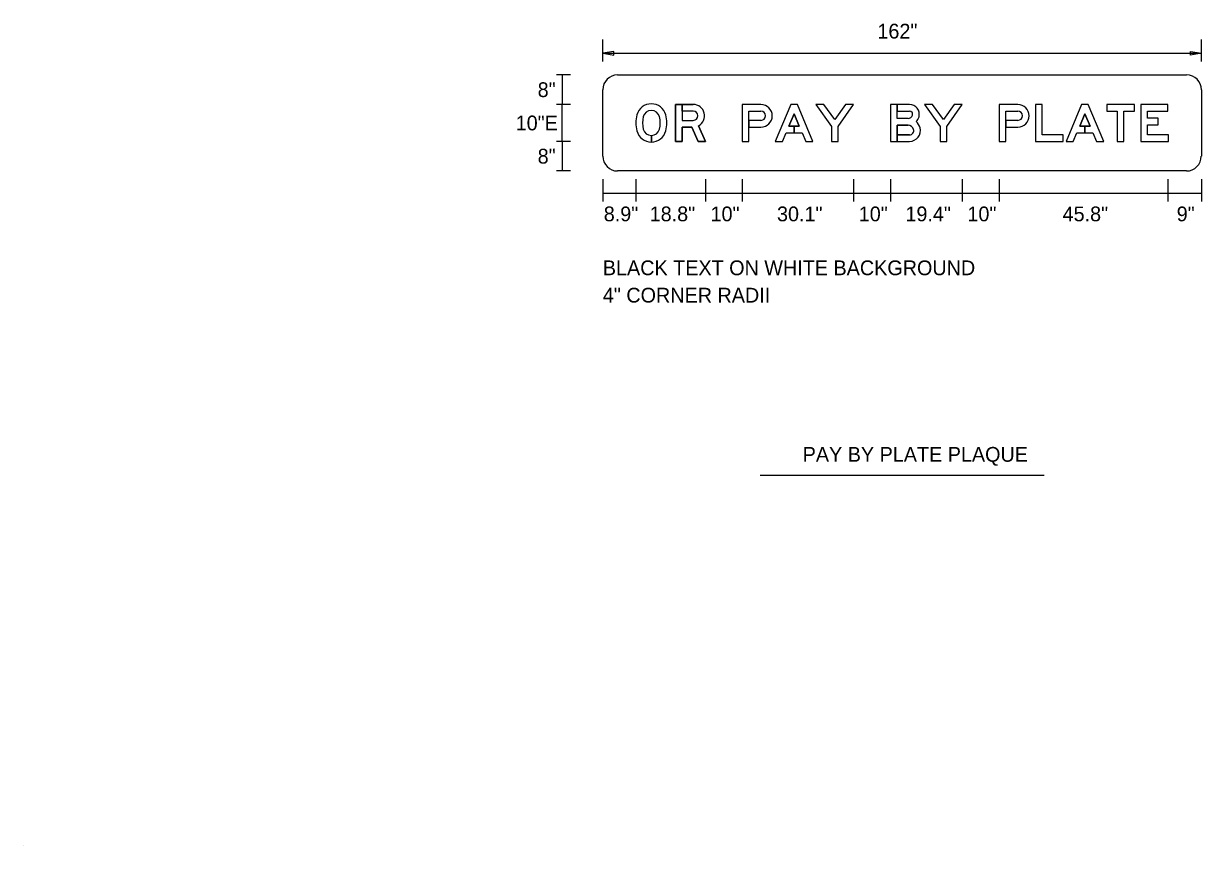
# Model space of a CAD drawing. Extents: x 10268312 to 10268472, y 2142583 to 2142688.
# Drawn here: x 10268312.2 to 10268372, y 2142583.3 to 2142625 of the extents above; entities that cross this region are included whole.
import ezdxf

# ---------------------------------------------------------------- set-up
doc = ezdxf.new("R2010")
doc.units = 0
for name, color, linetype in [('AdhocPoint_dp', 7, 'Continuous'), ('GSBWFill', 7, 'Continuous'), ('GSDims', 7, 'Continuous'), ('SignPanel', 7, 'Continuous'), ('TextLabel', 7, 'Continuous'), ('TextMisc', 7, 'Continuous')]:
    doc.layers.add(name, color=color, linetype=linetype)

msp = doc.modelspace()

# ---------------------------------------------------------------- linework, layer by layer
at = {"layer": 'AdhocPoint_dp'}
msp.add_line((10268312.23, 2142583.281), (10268312.23, 2142583.281), dxfattribs=at)
at = {"layer": 'GSBWFill'}
for p, q in [((10268342.368, 2142622.39), (10268371.236, 2142622.39)), ((10268341.618, 2142618.265), (10268341.618, 2142621.64)), ((10268371.986, 2142621.64), (10268371.986, 2142618.265)), ((10268371.236, 2142617.515), (10268342.368, 2142617.515))]:
    msp.add_line(p, q, dxfattribs=at)
for centre, start, end in [((10268342.368, 2142621.64), 90, 180), ((10268371.236, 2142621.64), 0, 90), ((10268342.368, 2142618.265), 180, 270), ((10268371.229, 2142618.265), 270, 0)]:
    msp.add_arc(centre, 0.75, start, end, dxfattribs=at)
at = {"layer": 'GSDims'}
for p, q in [((10268341.618, 2142623.07), (10268341.618, 2142624.195)), ((10268371.986, 2142623.07), (10268371.986, 2142624.195)), ((10268341.618, 2142623.492), (10268371.986, 2142623.492)), ((10268339.977, 2142622.39), (10268339.274, 2142622.39)), ((10268339.555, 2142622.39), (10268339.555, 2142620.89)), ((10268339.977, 2142620.89), (10268339.274, 2142620.89)), ((10268339.555, 2142619.015), (10268339.555, 2142620.89)), ((10268339.977, 2142619.015), (10268339.274, 2142619.015)), ((10268339.555, 2142619.015), (10268339.555, 2142617.515)), ((10268339.977, 2142617.515), (10268339.274, 2142617.515)), ((10268341.618, 2142617.093), (10268341.618, 2142615.968)), ((10268343.294, 2142617.093), (10268343.294, 2142615.968)), ((10268346.818, 2142617.093), (10268346.818, 2142615.968)), ((10268348.693, 2142617.093), (10268348.693, 2142615.968)), ((10268354.336, 2142617.093), (10268354.336, 2142615.968)), ((10268356.212, 2142617.093), (10268356.212, 2142615.968)), ((10268359.849, 2142617.093), (10268359.849, 2142615.968)), ((10268361.724, 2142617.093), (10268361.724, 2142615.968)), ((10268370.284, 2142617.093), (10268370.284, 2142615.968)), ((10268371.986, 2142617.093), (10268371.986, 2142615.968)), ((10268341.618, 2142616.39), (10268343.294, 2142616.39)), ((10268343.294, 2142616.39), (10268346.818, 2142616.39)), ((10268346.818, 2142616.39), (10268348.693, 2142616.39)), ((10268348.693, 2142616.39), (10268354.336, 2142616.39)), ((10268354.336, 2142616.39), (10268356.212, 2142616.39)), ((10268356.212, 2142616.39), (10268359.849, 2142616.39)), ((10268359.849, 2142616.39), (10268361.724, 2142616.39)), ((10268361.724, 2142616.39), (10268370.284, 2142616.39)), ((10268370.284, 2142616.39), (10268371.986, 2142616.39)), ((10268349.596, 2142602.067), (10268364.009, 2142602.067))]:
    msp.add_line(p, q, dxfattribs=at)
for points in [[(10268341.618, 2142623.492), (10268342.181, 2142623.398), (10268342.181, 2142623.586)], [(10268371.986, 2142623.492), (10268371.424, 2142623.398), (10268371.424, 2142623.586)]]:
    msp.add_lwpolyline(points, close=True, dxfattribs=at)
at = {"layer": 'SignPanel'}
for p, q in [((10268349.03, 2142620.552), (10268349.64, 2142620.552)), ((10268349.03, 2142620.552), (10268349.64, 2142620.552)), ((10268349.03, 2142620.552), (10268349.64, 2142620.552)), ((10268362.062, 2142620.552), (10268362.671, 2142620.552)), ((10268362.062, 2142620.552), (10268362.671, 2142620.552)), ((10268362.062, 2142620.552), (10268362.671, 2142620.552)), ((10268349.03, 2142619.746), (10268349.64, 2142619.746)), ((10268362.062, 2142619.746), (10268362.671, 2142619.746)), ((10268344.08, 2142618.982), (10268344.08, 2142619.319)), ((10268344.08, 2142619.319), (10268344.08, 2142618.982)), ((10268344.08, 2142618.982), (10268344.08, 2142619.319)), ((10268344.08, 2142619.319), (10268344.08, 2142618.982)), ((10268356.212, 2142619.015), (10268357.177, 2142619.015))]:
    msp.add_line(p, q, dxfattribs=at)
for points in [[(10268346.206, 2142620.89), (10268345.299, 2142620.89), (10268345.299, 2142619.015), (10268345.637, 2142619.015), (10268345.637, 2142619.746), (10268346.133, 2142619.746), (10268346.45, 2142619.015), (10268346.818, 2142619.015), (10268346.473, 2142619.812)], [(10268346.473, 2142619.812), (10268346.818, 2142619.015), (10268346.45, 2142619.015), (10268346.133, 2142619.746), (10268345.637, 2142619.746), (10268345.637, 2142619.015), (10268345.299, 2142619.015), (10268345.299, 2142620.89), (10268345.637, 2142620.89), (10268345.637, 2142620.083), (10268346.206, 2142620.083)], [(10268346.473, 2142619.812), (10268346.818, 2142619.015), (10268346.45, 2142619.015), (10268346.133, 2142619.746), (10268345.637, 2142619.746), (10268345.637, 2142619.015), (10268345.299, 2142619.015), (10268345.299, 2142620.89), (10268345.637, 2142620.89), (10268345.637, 2142620.083), (10268346.206, 2142620.083)], [(10268345.637, 2142620.552), (10268345.637, 2142620.89), (10268346.206, 2142620.89)], [(10268345.637, 2142620.552), (10268345.637, 2142620.89), (10268346.206, 2142620.89)], [(10268349.64, 2142620.89), (10268348.693, 2142620.89), (10268348.693, 2142619.015), (10268349.03, 2142619.015), (10268349.03, 2142619.746)], [(10268349.64, 2142620.89), (10268348.693, 2142620.89), (10268348.693, 2142619.015), (10268349.03, 2142619.015), (10268349.03, 2142620.552)], [(10268349.64, 2142620.89), (10268348.693, 2142620.89), (10268348.693, 2142619.015), (10268349.03, 2142619.015), (10268349.03, 2142620.552)], [(10268357.177, 2142620.89), (10268356.212, 2142620.89), (10268356.212, 2142619.015)], [(10268357.105, 2142620.177), (10268356.549, 2142620.177), (10268356.549, 2142620.89), (10268356.212, 2142620.89), (10268356.212, 2142619.015), (10268356.549, 2142619.015)], [(10268357.105, 2142620.177), (10268356.549, 2142620.177), (10268356.549, 2142620.89), (10268356.212, 2142620.89), (10268356.212, 2142619.015), (10268356.549, 2142619.015)], [(10268357.177, 2142620.89), (10268356.549, 2142620.89), (10268356.549, 2142620.552), (10268357.177, 2142620.552)], [(10268357.177, 2142620.89), (10268356.549, 2142620.89), (10268356.549, 2142620.552), (10268357.177, 2142620.552)], [(10268362.671, 2142620.89), (10268361.724, 2142620.89), (10268361.724, 2142619.015), (10268362.062, 2142619.015), (10268362.062, 2142619.746)], [(10268362.671, 2142620.89), (10268361.724, 2142620.89), (10268361.724, 2142619.015), (10268362.062, 2142619.015), (10268362.062, 2142620.552)], [(10268362.671, 2142620.89), (10268361.724, 2142620.89), (10268361.724, 2142619.015), (10268362.062, 2142619.015), (10268362.062, 2142620.552)], [(10268346.206, 2142620.552), (10268345.637, 2142620.552), (10268345.637, 2142620.083), (10268346.206, 2142620.083)], [(10268346.206, 2142620.552), (10268345.637, 2142620.552)], [(10268346.206, 2142620.552), (10268345.637, 2142620.552)], [(10268349.64, 2142620.083), (10268349.03, 2142620.083), (10268349.03, 2142620.552)], [(10268349.64, 2142620.083), (10268349.03, 2142620.083), (10268349.03, 2142619.746), (10268349.64, 2142619.746)], [(10268349.64, 2142620.083), (10268349.03, 2142620.083), (10268349.03, 2142619.746), (10268349.64, 2142619.746)], [(10268357.105, 2142620.177), (10268356.549, 2142620.177), (10268356.549, 2142620.552), (10268357.177, 2142620.552)], [(10268362.671, 2142620.083), (10268362.062, 2142620.083), (10268362.062, 2142620.552)], [(10268362.671, 2142620.083), (10268362.062, 2142620.083), (10268362.062, 2142619.746), (10268362.671, 2142619.746)], [(10268362.671, 2142620.083), (10268362.062, 2142620.083), (10268362.062, 2142619.746), (10268362.671, 2142619.746)], [(10268357.105, 2142619.84), (10268356.549, 2142619.84), (10268356.549, 2142619.352), (10268357.177, 2142619.352)], [(10268356.549, 2142619.015), (10268356.549, 2142619.84), (10268357.105, 2142619.84)], [(10268356.549, 2142619.015), (10268356.549, 2142619.84), (10268357.105, 2142619.84)], [(10268357.177, 2142619.352), (10268356.549, 2142619.352), (10268356.549, 2142619.015), (10268357.177, 2142619.015)], [(10268357.177, 2142619.352), (10268356.549, 2142619.352), (10268356.549, 2142619.015), (10268357.177, 2142619.015)]]:
    msp.add_lwpolyline(points, dxfattribs=at)
for points in [[(10268350.913, 2142619.455), (10268351.723, 2142619.455), (10268351.908, 2142619.015), (10268352.274, 2142619.015), (10268351.487, 2142620.89), (10268351.149, 2142620.89), (10268350.362, 2142619.015), (10268350.728, 2142619.015)], [(10268351.581, 2142619.793), (10268351.318, 2142619.793), (10268351.318, 2142619.455), (10268351.723, 2142619.455), (10268351.908, 2142619.015), (10268352.274, 2142619.015), (10268351.487, 2142620.89), (10268351.149, 2142620.89), (10268350.362, 2142619.015), (10268350.728, 2142619.015), (10268350.913, 2142619.455), (10268351.318, 2142619.455), (10268351.318, 2142619.793), (10268351.054, 2142619.793), (10268351.318, 2142620.42)], [(10268351.581, 2142619.793), (10268351.318, 2142619.793), (10268351.318, 2142619.455), (10268351.723, 2142619.455), (10268351.908, 2142619.015), (10268352.274, 2142619.015), (10268351.487, 2142620.89), (10268351.149, 2142620.89), (10268350.362, 2142619.015), (10268350.728, 2142619.015), (10268350.913, 2142619.455), (10268351.318, 2142619.455), (10268351.318, 2142619.793), (10268351.054, 2142619.793), (10268351.318, 2142620.42)], [(10268353.549, 2142619.774), (10268354.337, 2142620.89), (10268353.923, 2142620.89), (10268353.38, 2142620.12), (10268352.837, 2142620.89), (10268352.424, 2142620.89), (10268353.212, 2142619.774), (10268353.212, 2142619.015), (10268353.549, 2142619.015)], [(10268353.549, 2142619.774), (10268354.337, 2142620.89), (10268353.923, 2142620.89), (10268353.38, 2142620.12), (10268352.837, 2142620.89), (10268352.424, 2142620.89), (10268353.212, 2142619.774), (10268353.212, 2142619.015), (10268353.549, 2142619.015)], [(10268353.549, 2142619.774), (10268354.337, 2142620.89), (10268353.923, 2142620.89), (10268353.38, 2142620.12), (10268352.837, 2142620.89), (10268352.424, 2142620.89), (10268353.212, 2142619.774), (10268353.212, 2142619.015), (10268353.549, 2142619.015)], [(10268359.062, 2142619.774), (10268359.849, 2142620.89), (10268359.436, 2142620.89), (10268358.893, 2142620.12), (10268358.35, 2142620.89), (10268357.937, 2142620.89), (10268358.724, 2142619.774), (10268358.724, 2142619.015), (10268359.062, 2142619.015)], [(10268359.062, 2142619.774), (10268359.849, 2142620.89), (10268359.436, 2142620.89), (10268358.893, 2142620.12), (10268358.35, 2142620.89), (10268357.937, 2142620.89), (10268358.724, 2142619.774), (10268358.724, 2142619.015), (10268359.062, 2142619.015)], [(10268359.062, 2142619.774), (10268359.849, 2142620.89), (10268359.436, 2142620.89), (10268358.893, 2142620.12), (10268358.35, 2142620.89), (10268357.937, 2142620.89), (10268358.724, 2142619.774), (10268358.724, 2142619.015), (10268359.062, 2142619.015)], [(10268364.968, 2142619.015), (10268364.968, 2142619.343), (10268363.899, 2142619.343), (10268363.899, 2142620.89), (10268363.562, 2142620.89), (10268363.562, 2142619.015)], [(10268364.968, 2142619.015), (10268364.968, 2142619.343), (10268363.899, 2142619.343), (10268363.899, 2142620.89), (10268363.562, 2142620.89), (10268363.562, 2142619.015)], [(10268364.968, 2142619.015), (10268364.968, 2142619.343), (10268363.899, 2142619.343), (10268363.899, 2142620.89), (10268363.562, 2142620.89), (10268363.562, 2142619.015)], [(10268365.669, 2142619.455), (10268366.479, 2142619.455), (10268366.664, 2142619.015), (10268367.03, 2142619.015), (10268366.243, 2142620.89), (10268365.905, 2142620.89), (10268365.118, 2142619.015), (10268365.484, 2142619.015)], [(10268366.338, 2142619.793), (10268366.074, 2142619.793), (10268366.074, 2142619.455), (10268366.479, 2142619.455), (10268366.664, 2142619.015), (10268367.03, 2142619.015), (10268366.243, 2142620.89), (10268365.905, 2142620.89), (10268365.118, 2142619.015), (10268365.484, 2142619.015), (10268365.669, 2142619.455), (10268366.074, 2142619.455), (10268366.074, 2142619.793), (10268365.811, 2142619.793), (10268366.074, 2142620.42)], [(10268366.338, 2142619.793), (10268366.074, 2142619.793), (10268366.074, 2142619.455), (10268366.479, 2142619.455), (10268366.664, 2142619.015), (10268367.03, 2142619.015), (10268366.243, 2142620.89), (10268365.905, 2142620.89), (10268365.118, 2142619.015), (10268365.484, 2142619.015), (10268365.669, 2142619.455), (10268366.074, 2142619.455), (10268366.074, 2142619.793), (10268365.811, 2142619.793), (10268366.074, 2142620.42)], [(10268367.18, 2142620.552), (10268367.715, 2142620.552), (10268367.715, 2142619.015), (10268368.052, 2142619.015), (10268368.052, 2142620.552), (10268368.587, 2142620.552), (10268368.587, 2142620.89), (10268367.18, 2142620.89)], [(10268367.18, 2142620.552), (10268367.715, 2142620.552), (10268367.715, 2142619.015), (10268368.052, 2142619.015), (10268368.052, 2142620.552), (10268368.587, 2142620.552), (10268368.587, 2142620.89), (10268367.18, 2142620.89)], [(10268367.18, 2142620.552), (10268367.715, 2142620.552), (10268367.715, 2142619.015), (10268368.052, 2142619.015), (10268368.052, 2142620.552), (10268368.587, 2142620.552), (10268368.587, 2142620.89), (10268367.18, 2142620.89)], [(10268370.312, 2142619.352), (10268369.243, 2142619.352), (10268369.243, 2142619.856), (10268369.796, 2142619.856), (10268369.796, 2142620.194), (10268369.243, 2142620.194), (10268369.243, 2142620.552), (10268370.284, 2142620.552), (10268370.284, 2142620.89), (10268368.905, 2142620.89), (10268368.905, 2142619.015), (10268370.312, 2142619.015)], [(10268370.312, 2142619.352), (10268369.243, 2142619.352), (10268369.243, 2142619.856), (10268369.796, 2142619.856), (10268369.796, 2142620.194), (10268369.243, 2142620.194), (10268369.243, 2142620.552), (10268370.284, 2142620.552), (10268370.284, 2142620.89), (10268368.905, 2142620.89), (10268368.905, 2142619.015), (10268370.312, 2142619.015)], [(10268370.312, 2142619.352), (10268369.243, 2142619.352), (10268369.243, 2142619.856), (10268369.796, 2142619.856), (10268369.796, 2142620.194), (10268369.243, 2142620.194), (10268369.243, 2142620.552), (10268370.284, 2142620.552), (10268370.284, 2142620.89), (10268368.905, 2142620.89), (10268368.905, 2142619.015), (10268370.312, 2142619.015)], [(10268351.581, 2142619.793), (10268351.318, 2142620.42), (10268351.054, 2142619.793)], [(10268366.338, 2142619.793), (10268366.074, 2142620.42), (10268365.811, 2142619.793)]]:
    msp.add_lwpolyline(points, close=True, dxfattribs=at)
for centre, radius, start, end in [((10268344.08, 2142620.163), 0.76, 14.96177, 165.03823), ((10268344.08, 2142620.163), 0.76, 14.96177, 165.03823), ((10268344.08, 2142620.163), 0.76, 14.96177, 165.03823), ((10268344.08, 2142620.163), 0.422, 14.96177, 165.03823), ((10268344.08, 2142620.163), 0.422, 14.96177, 165.03823), ((10268344.08, 2142620.163), 0.422, 14.96177, 165.03823), ((10268346.206, 2142620.318), 0.572, 297.837, 90), ((10268346.206, 2142620.318), 0.572, 297.837, 90), ((10268346.206, 2142620.318), 0.572, 297.837, 90), ((10268349.64, 2142620.318), 0.572, 270, 90), ((10268349.64, 2142620.318), 0.572, 270, 90), ((10268349.64, 2142620.318), 0.572, 270, 90), ((10268357.177, 2142620.393), 0.497, 345.52249, 90), ((10268357.177, 2142620.393), 0.497, 345.52249, 90), ((10268357.177, 2142620.393), 0.497, 345.52249, 90), ((10268362.671, 2142620.318), 0.572, 270, 90), ((10268362.671, 2142620.318), 0.572, 270, 90), ((10268362.671, 2142620.318), 0.572, 270, 90), ((10268344.868, 2142619.952), 1.575, 165.03823, 194.96177), ((10268344.868, 2142619.952), 1.575, 165.03823, 194.96177), ((10268344.868, 2142619.952), 1.575, 165.03823, 194.96177), ((10268344.868, 2142619.952), 1.238, 165.03823, 194.96177), ((10268344.868, 2142619.952), 1.238, 165.03823, 194.96177), ((10268344.868, 2142619.952), 1.238, 165.03823, 194.96177), ((10268343.293, 2142619.952), 1.238, 345.03823, 14.96177), ((10268343.293, 2142619.952), 1.238, 345.03823, 14.96177), ((10268343.293, 2142619.952), 1.238, 345.03823, 14.96177), ((10268343.293, 2142619.952), 1.575, 345.03823, 14.96177), ((10268343.293, 2142619.952), 1.575, 345.03823, 14.96177), ((10268343.293, 2142619.952), 1.575, 345.03823, 14.96177), ((10268346.206, 2142620.318), 0.234, 270, 90), ((10268346.206, 2142620.318), 0.234, 270, 90), ((10268346.206, 2142620.318), 0.234, 270, 90), ((10268349.64, 2142620.318), 0.234, 270, 90), ((10268349.64, 2142620.318), 0.234, 270, 90), ((10268349.64, 2142620.318), 0.234, 270, 90), ((10268357.105, 2142620.412), 0.234, 270, 345.52249), ((10268357.105, 2142620.412), 0.234, 270, 345.52249), ((10268357.105, 2142620.412), 0.234, 270, 345.52249), ((10268357.177, 2142620.393), 0.159, 345.52249, 90), ((10268357.177, 2142620.393), 0.159, 345.52249, 90), ((10268357.177, 2142620.393), 0.159, 345.52249, 90), ((10268357.105, 2142620.412), 0.572, 316.7114, 345.52249), ((10268357.105, 2142620.412), 0.572, 316.7114, 345.52249), ((10268357.105, 2142620.412), 0.572, 316.7114, 345.52249), ((10268357.105, 2142619.549), 0.628, 14.47751, 48.4921), ((10268357.105, 2142619.549), 0.628, 14.47751, 48.4921), ((10268357.105, 2142619.549), 0.628, 14.47751, 48.4921), ((10268362.671, 2142620.318), 0.234, 270, 90), ((10268362.671, 2142620.318), 0.234, 270, 90), ((10268362.671, 2142620.318), 0.234, 270, 90), ((10268344.08, 2142619.742), 0.76, 194.96177, 345.03823), ((10268344.08, 2142619.742), 0.76, 194.96177, 270), ((10268344.08, 2142619.742), 0.76, 194.96177, 270), ((10268344.08, 2142619.742), 0.422, 194.96177, 345.03823), ((10268344.08, 2142619.742), 0.422, 194.96177, 270), ((10268344.08, 2142619.742), 0.422, 194.96177, 270), ((10268344.08, 2142619.742), 0.422, 270.01272, 345.03823), ((10268344.08, 2142619.742), 0.422, 270.01272, 345.03823), ((10268344.08, 2142619.742), 0.76, 270.00707, 345.03823), ((10268344.08, 2142619.742), 0.76, 270.00707, 345.03823), ((10268357.105, 2142619.549), 0.291, 14.47751, 90), ((10268357.105, 2142619.549), 0.291, 14.47751, 90), ((10268357.105, 2142619.549), 0.291, 14.47751, 90), ((10268357.177, 2142619.568), 0.553, 270, 14.47751), ((10268357.177, 2142619.568), 0.553, 270, 14.47751), ((10268357.177, 2142619.568), 0.553, 270, 14.47751), ((10268357.177, 2142619.568), 0.216, 270, 14.47751), ((10268357.177, 2142619.568), 0.216, 270, 14.47751), ((10268357.177, 2142619.568), 0.216, 270, 14.47751)]:
    msp.add_arc(centre, radius, start, end, dxfattribs=at)

# ---------------------------------------------------------------- texts
at = {"layer": 'GSDims'}
for s, p in [('162"', (10268355.548, 2142624.236)), ('8"', (10268338.312, 2142621.265)), ('10"E', (10268337.196, 2142619.577)), ('8"', (10268338.312, 2142617.89)), ('8.9"', (10268341.665, 2142614.961)), ('18.8"', (10268343.995, 2142614.961)), ('10"', (10268347.082, 2142614.961)), ('30.1"', (10268350.454, 2142614.961)), ('10"', (10268354.601, 2142614.961)), ('19.4"', (10268356.97, 2142614.961)), ('10"', (10268360.114, 2142614.961)), ('45.8"', (10268364.943, 2142614.961)), ('9"', (10268370.731, 2142614.961))]:
    msp.add_text(s, height=0.75, dxfattribs=at).set_placement(p)
at = {"layer": 'TextLabel'}
msp.add_text('PAY BY PLATE PLAQUE', height=0.75, dxfattribs=at).set_placement((10268351.757, 2142602.756))
at = {"layer": 'TextMisc'}
for s, p in [('BLACK TEXT ON WHITE BACKGROUND', (10268341.618, 2142612.224)), ('4" CORNER RADII', (10268341.618, 2142610.836))]:
    msp.add_text(s, height=0.75, dxfattribs=at).set_placement(p)

doc.saveas('drawing.dxf')
